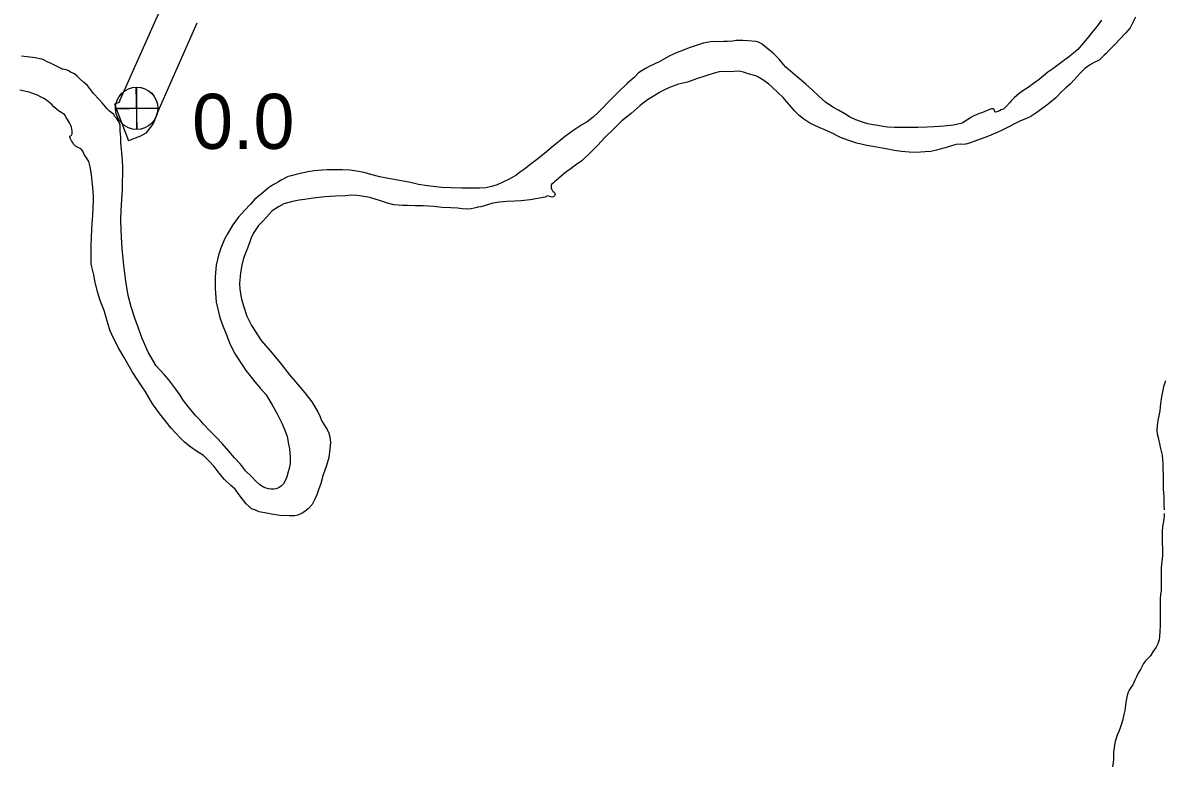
# Model space of a CAD drawing. Extents: x -939622 to -934222, y 1383701 to 1385301.
# Drawn here: x -935712.73 to -935686.47, y 1384159.44 to 1384176.56 of the extents above; entities that cross this region are included whole.
import ezdxf

# ---------------------------------------------------------------- set-up
doc = ezdxf.new("R2010")
doc.units = 0
for name, color, linetype in [('Level 10', 7, 'Continuous'), ('Level 25', 7, 'Continuous'), ('Level 26', 7, 'Continuous'), ('Level 9', 7, 'Continuous')]:
    doc.layers.add(name, color=color, linetype=linetype)

msp = doc.modelspace()

# ---------------------------------------------------------------- linework, layer by layer
at = {"layer": 'Level 10'}
for points in [[(-935709.55, 1384176.91), (-935710.495, 1384174.776), (-935710.512, 1384174.722), (-935710.62, 1384174.681)], [(-935708.727, 1384176.546), (-935709.651, 1384174.459), (-935709.679, 1384174.37), (-935709.719, 1384174.267), (-935709.77, 1384174.182), (-935709.82, 1384174.114), (-935709.902, 1384174.018), (-935710.02, 1384173.946), (-935710.149, 1384173.898), (-935710.297, 1384173.841)], [(-935710.62, 1384174.681), (-935710.297, 1384173.841)]]:
    msp.add_lwpolyline(points, dxfattribs=at)
at = {"layer": 'Level 25'}
for p, q in [((-935710.099, 1384174.1), (-935710.122, 1384175.077)), ((-935710.599, 1384174.577), (-935709.622, 1384174.6))]:
    msp.add_line(p, q, dxfattribs=at)
msp.add_circle((-935710.11, 1384174.589), 0.488, dxfattribs=at)
at = {"layer": 'Level 26'}
for p, q in [((-935710.11, 1384174.101), (-935710.11, 1384175.076)), ((-935710.598, 1384174.589), (-935709.623, 1384174.589))]:
    msp.add_line(p, q, dxfattribs=at)
msp.add_circle((-935710.11, 1384174.589), 0.487, dxfattribs=at)
at = {"layer": 'Level 9'}
for points in [[(-935687.124, 1384176.684), (-935687.202, 1384176.535), (-935687.251, 1384176.441), (-935687.354, 1384176.316), (-935687.492, 1384176.171), (-935687.583, 1384176.07), (-935687.653, 1384176.003), (-935687.741, 1384175.92), (-935687.803, 1384175.852), (-935687.847, 1384175.809), (-935687.959, 1384175.699), (-935688.074, 1384175.642), (-935688.181, 1384175.583), (-935688.29, 1384175.506), (-935688.399, 1384175.395), (-935688.54, 1384175.248), (-935688.631, 1384175.144), (-935688.731, 1384175.058), (-935688.831, 1384174.971), (-935688.96, 1384174.833), (-935689.087, 1384174.722), (-935689.169, 1384174.664), (-935689.281, 1384174.574), (-935689.42, 1384174.478), (-935689.533, 1384174.401), (-935689.637, 1384174.357), (-935689.77, 1384174.3), (-935689.898, 1384174.237), (-935690.028, 1384174.171), (-935690.117, 1384174.127), (-935690.192, 1384174.087), (-935690.295, 1384174.037), (-935690.51, 1384173.951), (-935690.822, 1384173.834), (-935690.905, 1384173.805), (-935691, 1384173.773), (-935691.009, 1384173.767), (-935691.069, 1384173.757), (-935691.147, 1384173.761), (-935691.258, 1384173.753), (-935691.407, 1384173.708), (-935691.505, 1384173.679), (-935691.6, 1384173.653), (-935691.705, 1384173.627), (-935691.833, 1384173.597), (-935691.965, 1384173.585), (-935692.075, 1384173.577), (-935692.192, 1384173.572), (-935692.336, 1384173.581), (-935692.507, 1384173.593), (-935692.682, 1384173.62), (-935692.826, 1384173.647), (-935692.955, 1384173.668), (-935693.127, 1384173.698), (-935693.31, 1384173.731), (-935693.542, 1384173.783), (-935693.726, 1384173.846), (-935693.917, 1384173.92), (-935694.138, 1384174.03), (-935694.262, 1384174.082), (-935694.404, 1384174.146), (-935694.618, 1384174.244), (-935694.755, 1384174.337), (-935694.868, 1384174.425), (-935694.972, 1384174.532), (-935695.046, 1384174.624), (-935695.159, 1384174.748), (-935695.236, 1384174.84), (-935695.352, 1384174.946), (-935695.484, 1384175.079), (-935695.56, 1384175.146), (-935695.676, 1384175.228), (-935695.815, 1384175.313), (-935695.866, 1384175.333), (-935696.038, 1384175.381), (-935696.15, 1384175.421), (-935696.237, 1384175.443), (-935696.486, 1384175.432), (-935696.573, 1384175.433), (-935696.705, 1384175.425), (-935696.824, 1384175.401), (-935697.011, 1384175.337), (-935697.229, 1384175.264), (-935697.437, 1384175.194), (-935697.64, 1384175.142), (-935697.851, 1384175.065), (-935697.994, 1384174.996), (-935698.077, 1384174.952), (-935698.204, 1384174.878), (-935698.352, 1384174.781), (-935698.526, 1384174.652), (-935698.729, 1384174.47), (-935698.944, 1384174.3), (-935699.132, 1384174.113)], [(-935687.905, 1384176.621), (-935688.004, 1384176.48), (-935688.121, 1384176.34), (-935688.241, 1384176.196), (-935688.455, 1384175.945), (-935688.552, 1384175.856), (-935688.667, 1384175.769), (-935688.782, 1384175.68), (-935689.03, 1384175.497), (-935689.143, 1384175.417), (-935689.34, 1384175.25), (-935689.476, 1384175.16), (-935689.597, 1384175.071), (-935689.698, 1384175.005), (-935689.804, 1384174.928), (-935689.916, 1384174.833), (-935689.981, 1384174.768), (-935690.025, 1384174.716), (-935690.086, 1384174.643), (-935690.121, 1384174.609), (-935690.165, 1384174.572), (-935690.213, 1384174.553), (-935690.252, 1384174.534), (-935690.296, 1384174.518), (-935690.32, 1384174.509), (-935690.35, 1384174.502), (-935690.362, 1384174.505), (-935690.365, 1384174.514), (-935690.368, 1384174.532), (-935690.372, 1384174.547), (-935690.378, 1384174.562), (-935690.393, 1384174.576), (-935690.402, 1384174.579), (-935690.441, 1384174.576), (-935690.459, 1384174.569), (-935690.593, 1384174.515), (-935690.649, 1384174.493), (-935690.715, 1384174.468), (-935690.795, 1384174.439), (-935690.849, 1384174.414), (-935690.896, 1384174.383), (-935691.118, 1384174.249), (-935691.312, 1384174.2), (-935691.53, 1384174.178), (-935691.755, 1384174.164), (-935691.919, 1384174.152), (-935692.138, 1384174.148), (-935692.33, 1384174.147), (-935692.515, 1384174.144), (-935692.671, 1384174.146), (-935692.836, 1384174.158), (-935692.933, 1384174.171), (-935693.053, 1384174.193), (-935693.161, 1384174.212), (-935693.287, 1384174.228), (-935693.405, 1384174.268), (-935693.565, 1384174.322), (-935693.704, 1384174.391), (-935693.814, 1384174.461), (-935693.962, 1384174.543), (-935694.09, 1384174.612), (-935694.26, 1384174.732), (-935694.409, 1384174.871), (-935694.562, 1384175.009), (-935694.712, 1384175.142), (-935694.864, 1384175.274), (-935695.008, 1384175.395), (-935695.172, 1384175.536), (-935695.225, 1384175.601), (-935695.326, 1384175.72), (-935695.439, 1384175.835), (-935695.546, 1384175.929), (-935695.653, 1384176.014), (-935695.714, 1384176.067), (-935695.801, 1384176.111), (-935695.862, 1384176.125), (-935696.042, 1384176.139), (-935696.162, 1384176.149), (-935696.315, 1384176.149), (-935696.392, 1384176.138), (-935696.518, 1384176.127), (-935696.608, 1384176.125), (-935696.746, 1384176.119), (-935696.842, 1384176.123), (-935696.904, 1384176.119), (-935697.078, 1384176.092), (-935697.372, 1384175.99), (-935697.714, 1384175.862), (-935697.869, 1384175.784), (-935698.07, 1384175.669), (-935698.302, 1384175.562), (-935698.405, 1384175.506), (-935698.559, 1384175.403), (-935698.656, 1384175.305), (-935698.824, 1384175.157)], [(-935712.758, 1384175.796), (-935712.632, 1384175.778), (-935712.448, 1384175.759), (-935712.298, 1384175.73), (-935712.231, 1384175.698), (-935712.182, 1384175.669), (-935712.1, 1384175.635), (-935712.055, 1384175.615), (-935711.982, 1384175.572), (-935711.811, 1384175.489)], [(-935707.077, 1384165.827), (-935707.131, 1384165.844), (-935707.192, 1384165.87), (-935707.277, 1384165.923), (-935707.371, 1384166.005), (-935707.472, 1384166.109), (-935707.604, 1384166.241), (-935707.721, 1384166.399), (-935707.859, 1384166.54), (-935707.991, 1384166.697), (-935708.141, 1384166.869), (-935708.264, 1384167.002), (-935708.426, 1384167.164), (-935708.573, 1384167.318), (-935708.653, 1384167.407), (-935708.748, 1384167.507), (-935708.895, 1384167.682), (-935709.04, 1384167.872), (-935709.111, 1384167.985), (-935709.231, 1384168.151), (-935709.373, 1384168.335), (-935709.474, 1384168.456), (-935709.661, 1384168.66), (-935709.85, 1384168.972), (-935709.986, 1384169.289), (-935710.062, 1384169.501), (-935710.145, 1384169.734), (-935710.237, 1384170.015), (-935710.305, 1384170.276), (-935710.363, 1384170.612), (-935710.407, 1384170.981), (-935710.434, 1384171.273), (-935710.453, 1384171.483), (-935710.468, 1384171.784), (-935710.473, 1384172.021), (-935710.468, 1384172.247), (-935710.455, 1384172.479), (-935710.439, 1384172.708), (-935710.434, 1384172.901), (-935710.431, 1384173.076), (-935710.431, 1384173.226), (-935710.441, 1384173.394), (-935710.45, 1384173.557), (-935710.461, 1384173.647), (-935710.473, 1384173.791), (-935710.475, 1384173.917), (-935710.483, 1384174.002), (-935710.488, 1384174.071), (-935710.49, 1384174.203), (-935710.5, 1384174.224), (-935710.516, 1384174.269), (-935710.534, 1384174.299), (-935710.577, 1384174.358), (-935710.617, 1384174.402), (-935710.645, 1384174.45), (-935710.733, 1384174.52), (-935710.792, 1384174.576), (-935710.905, 1384174.716), (-935710.973, 1384174.793), (-935711.104, 1384174.931), (-935711.24, 1384175.112), (-935711.332, 1384175.192), (-935711.408, 1384175.26), (-935711.484, 1384175.33), (-935711.539, 1384175.38), (-935711.633, 1384175.421), (-935711.672, 1384175.45), (-935711.73, 1384175.473), (-935711.811, 1384175.489)], [(-935711.775, 1384174.443), (-935711.908, 1384174.53), (-935712.015, 1384174.626), (-935712.068, 1384174.682), (-935712.147, 1384174.747), (-935712.233, 1384174.805), (-935712.324, 1384174.85), (-935712.397, 1384174.888), (-935712.503, 1384174.933), (-935712.582, 1384174.961), (-935712.663, 1384174.977), (-935712.799, 1384175.004)], [(-935698.824, 1384175.157), (-935699.033, 1384174.961), (-935699.139, 1384174.856), (-935699.268, 1384174.724), (-935699.373, 1384174.611), (-935699.485, 1384174.5), (-935699.603, 1384174.387), (-935699.747, 1384174.281), (-935699.869, 1384174.207), (-935700.076, 1384174.073), (-935700.244, 1384173.944), (-935700.53, 1384173.715), (-935700.727, 1384173.549), (-935700.91, 1384173.404), (-935701.067, 1384173.289), (-935701.188, 1384173.185), (-935701.279, 1384173.123), (-935701.388, 1384173.039), (-935701.551, 1384172.949), (-935701.688, 1384172.886), (-935701.819, 1384172.826), (-935701.947, 1384172.785), (-935702.075, 1384172.758), (-935702.225, 1384172.752), (-935702.473, 1384172.747), (-935702.632, 1384172.75), (-935702.881, 1384172.757), (-935703.094, 1384172.768), (-935703.419, 1384172.801), (-935703.629, 1384172.836), (-935703.81, 1384172.88), (-935704.105, 1384172.935), (-935704.363, 1384172.984), (-935704.514, 1384173.011), (-935704.719, 1384173.064), (-935704.878, 1384173.109), (-935705.056, 1384173.142), (-935705.2, 1384173.163), (-935705.377, 1384173.172), (-935705.566, 1384173.174), (-935705.725, 1384173.174), (-935705.854, 1384173.168), (-935706.03, 1384173.147), (-935706.173, 1384173.123), (-935706.343, 1384173.084), (-935706.439, 1384173.064), (-935706.555, 1384173.031), (-935706.627, 1384173.018), (-935706.671, 1384172.999), (-935706.787, 1384172.933), (-935706.849, 1384172.893), (-935706.988, 1384172.818), (-935707.077, 1384172.756), (-935707.248, 1384172.611), (-935707.39, 1384172.497), (-935707.495, 1384172.381), (-935707.627, 1384172.237), (-935707.697, 1384172.157), (-935707.776, 1384172.071), (-935707.902, 1384171.903), (-935708.021, 1384171.702), (-935708.087, 1384171.574), (-935708.176, 1384171.365), (-935708.229, 1384171.21), (-935708.285, 1384170.981), (-935708.306, 1384170.709), (-935708.307, 1384170.444), (-935708.282, 1384170.129), (-935708.197, 1384169.775), (-935708.13, 1384169.584), (-935708.061, 1384169.411), (-935707.976, 1384169.19), (-935707.86, 1384168.951), (-935707.742, 1384168.776), (-935707.671, 1384168.663), (-935707.597, 1384168.55), (-935707.501, 1384168.426), (-935707.391, 1384168.292), (-935707.259, 1384168.141), (-935707.139, 1384167.996), (-935707.059, 1384167.874), (-935706.981, 1384167.735), (-935706.881, 1384167.556), (-935706.772, 1384167.341), (-935706.7, 1384167.18), (-935706.649, 1384167.034), (-935706.615, 1384166.86), (-935706.598, 1384166.749), (-935706.582, 1384166.556), (-935706.579, 1384166.415), (-935706.601, 1384166.294), (-935706.623, 1384166.222), (-935706.654, 1384166.107), (-935706.7, 1384165.994), (-935706.732, 1384165.946), (-935706.776, 1384165.897), (-935706.832, 1384165.856), (-935706.903, 1384165.825), (-935706.954, 1384165.821), (-935707.02, 1384165.819), (-935707.077, 1384165.827)], [(-935711.629, 1384174.196), (-935711.66, 1384174.255), (-935711.701, 1384174.333), (-935711.741, 1384174.392), (-935711.756, 1384174.422), (-935711.775, 1384174.443)], [(-935705.816, 1384167.339), (-935705.757, 1384167.238), (-935705.729, 1384167.193), (-935705.691, 1384167.107), (-935705.666, 1384167.023), (-935705.654, 1384166.891), (-935705.666, 1384166.746), (-935705.692, 1384166.55), (-935705.742, 1384166.368), (-935705.827, 1384166.126), (-935705.875, 1384165.953), (-935705.929, 1384165.802), (-935705.962, 1384165.69), (-935706.008, 1384165.593), (-935706.072, 1384165.465), (-935706.163, 1384165.37), (-935706.242, 1384165.305), (-935706.304, 1384165.268), (-935706.399, 1384165.224), (-935706.48, 1384165.21), (-935706.603, 1384165.205), (-935706.816, 1384165.212), (-935707.011, 1384165.245), (-935707.162, 1384165.275), (-935707.255, 1384165.291), (-935707.291, 1384165.299), (-935707.376, 1384165.334), (-935707.379, 1384165.334), (-935707.466, 1384165.368), (-935707.478, 1384165.374), (-935707.512, 1384165.41), (-935707.591, 1384165.48), (-935707.755, 1384165.691), (-935707.847, 1384165.818), (-935707.948, 1384165.907), (-935708.088, 1384166.045), (-935708.214, 1384166.19), (-935708.331, 1384166.339), (-935708.451, 1384166.475), (-935708.57, 1384166.596), (-935708.731, 1384166.695), (-935708.865, 1384166.789), (-935709.011, 1384166.906), (-935709.118, 1384167.012), (-935709.317, 1384167.222), (-935709.579, 1384167.551), (-935709.745, 1384167.786), (-935709.916, 1384168.074), (-935709.972, 1384168.154), (-935710.089, 1384168.336), (-935710.21, 1384168.514), (-935710.328, 1384168.725), (-935710.396, 1384168.85), (-935710.523, 1384169.056), (-935710.648, 1384169.3), (-935710.724, 1384169.464), (-935710.765, 1384169.611), (-935710.817, 1384169.772), (-935710.862, 1384169.931), (-935710.951, 1384170.164), (-935711.005, 1384170.337), (-935711.064, 1384170.577), (-935711.1, 1384170.751), (-935711.156, 1384170.997), (-935711.159, 1384171.147), (-935711.159, 1384171.261), (-935711.159, 1384171.427), (-935711.148, 1384171.614), (-935711.146, 1384171.797), (-935711.133, 1384171.936), (-935711.122, 1384172.126), (-935711.111, 1384172.301), (-935711.105, 1384172.445), (-935711.104, 1384172.566), (-935711.109, 1384172.668), (-935711.117, 1384172.764), (-935711.146, 1384172.977), (-935711.153, 1384173.067), (-935711.184, 1384173.241), (-935711.197, 1384173.301), (-935711.211, 1384173.367), (-935711.251, 1384173.424), (-935711.316, 1384173.528), (-935711.334, 1384173.566), (-935711.35, 1384173.599), (-935711.378, 1384173.641), (-935711.405, 1384173.661), (-935711.466, 1384173.69), (-935711.517, 1384173.719), (-935711.557, 1384173.755), (-935711.588, 1384173.808), (-935711.61, 1384173.838), (-935711.635, 1384173.886), (-935711.653, 1384173.924), (-935711.648, 1384173.946), (-935711.63, 1384173.958), (-935711.609, 1384173.973), (-935711.595, 1384174.001), (-935711.599, 1384174.067), (-935711.613, 1384174.145), (-935711.629, 1384174.196)], [(-935699.132, 1384174.113), (-935699.332, 1384173.928), (-935699.505, 1384173.732), (-935699.661, 1384173.576), (-935699.864, 1384173.382), (-935700.015, 1384173.28), (-935700.144, 1384173.178), (-935700.201, 1384173.141), (-935700.286, 1384173.07), (-935700.404, 1384172.974), (-935700.457, 1384172.928), (-935700.492, 1384172.897), (-935700.519, 1384172.876), (-935700.563, 1384172.833), (-935700.569, 1384172.815), (-935700.574, 1384172.793), (-935700.574, 1384172.781), (-935700.573, 1384172.754), (-935700.57, 1384172.742), (-935700.558, 1384172.719), (-935700.542, 1384172.692), (-935700.53, 1384172.677), (-935700.505, 1384172.656), (-935700.487, 1384172.63), (-935700.487, 1384172.627), (-935700.483, 1384172.609), (-935700.495, 1384172.575), (-935700.515, 1384172.554), (-935700.551, 1384172.541), (-935700.602, 1384172.561), (-935700.654, 1384172.572), (-935700.71, 1384172.544), (-935701.053, 1384172.48), (-935701.122, 1384172.476), (-935701.26, 1384172.461), (-935701.412, 1384172.452), (-935701.592, 1384172.442), (-935701.763, 1384172.43), (-935701.918, 1384172.403), (-935702.061, 1384172.361), (-935702.192, 1384172.319), (-935702.264, 1384172.309), (-935702.273, 1384172.306), (-935702.413, 1384172.276), (-935702.5, 1384172.268), (-935702.617, 1384172.278), (-935702.731, 1384172.288), (-935702.878, 1384172.294), (-935703.082, 1384172.305), (-935703.271, 1384172.325), (-935703.52, 1384172.341), (-935703.7, 1384172.341), (-935703.88, 1384172.349), (-935703.997, 1384172.353), (-935704.192, 1384172.364), (-935704.337, 1384172.401), (-935704.524, 1384172.463), (-935704.62, 1384172.494), (-935704.747, 1384172.534), (-935704.93, 1384172.566), (-935705.041, 1384172.579), (-935705.165, 1384172.592), (-935705.311, 1384172.577), (-935705.536, 1384172.564), (-935705.784, 1384172.553), (-935706.05, 1384172.52), (-935706.251, 1384172.492), (-935706.37, 1384172.475), (-935706.528, 1384172.445), (-935706.722, 1384172.387), (-935706.846, 1384172.318), (-935706.994, 1384172.225), (-935707.199, 1384171.995), (-935707.241, 1384171.961), (-935707.305, 1384171.894), (-935707.433, 1384171.708), (-935707.473, 1384171.608), (-935707.516, 1384171.489), (-935707.579, 1384171.329), (-935707.65, 1384171.138), (-935707.688, 1384170.974), (-935707.721, 1384170.799), (-935707.743, 1384170.552), (-935707.737, 1384170.42), (-935707.699, 1384170.195), (-935707.645, 1384170.015), (-935707.575, 1384169.806), (-935707.471, 1384169.591), (-935707.248, 1384169.24), (-935706.991, 1384168.95), (-935706.806, 1384168.725), (-935706.594, 1384168.449), (-935706.367, 1384168.183), (-935706.241, 1384168.038), (-935706.081, 1384167.833), (-935705.988, 1384167.679), (-935705.944, 1384167.601), (-935705.891, 1384167.485), (-935705.882, 1384167.464), (-935705.859, 1384167.404), (-935705.816, 1384167.339)], [(-935686.433, 1384168.312), (-935686.481, 1384168.173), (-935686.53, 1384167.946), (-935686.548, 1384167.792), (-935686.563, 1384167.627), (-935686.582, 1384167.545), (-935686.615, 1384167.403), (-935686.628, 1384167.288), (-935686.631, 1384167.174), (-935686.627, 1384167.096), (-935686.607, 1384167.009), (-935686.587, 1384166.931), (-935686.571, 1384166.871), (-935686.555, 1384166.79), (-935686.509, 1384166.604), (-935686.496, 1384166.415), (-935686.496, 1384166.292), (-935686.487, 1384166.132), (-935686.487, 1384165.991), (-935686.487, 1384165.825), (-935686.477, 1384165.645), (-935686.471, 1384165.461), (-935686.465, 1384165.344)], [(-935686.463, 1384165.257), (-935686.468, 1384165.202), (-935686.481, 1384165.079), (-935686.502, 1384164.958), (-935686.512, 1384164.849), (-935686.51, 1384164.759), (-935686.508, 1384164.636), (-935686.506, 1384164.392), (-935686.507, 1384164.29), (-935686.519, 1384164.154), (-935686.534, 1384164.015), (-935686.538, 1384163.916), (-935686.533, 1384163.835), (-935686.534, 1384163.708), (-935686.535, 1384163.621), (-935686.533, 1384163.534), (-935686.538, 1384163.47), (-935686.549, 1384163.401), (-935686.561, 1384163.295), (-935686.557, 1384163.235), (-935686.556, 1384163.157), (-935686.554, 1384163.064), (-935686.557, 1384162.919), (-935686.56, 1384162.781), (-935686.561, 1384162.681), (-935686.564, 1384162.546), (-935686.571, 1384162.425), (-935686.584, 1384162.35), (-935686.612, 1384162.262), (-935686.653, 1384162.186), (-935686.725, 1384162.076), (-935686.781, 1384161.985), (-935686.898, 1384161.868), (-935686.939, 1384161.81), (-935686.982, 1384161.728), (-935687.014, 1384161.667), (-935687.057, 1384161.6), (-935687.106, 1384161.503), (-935687.138, 1384161.421), (-935687.164, 1384161.372), (-935687.19, 1384161.318), (-935687.21, 1384161.284), (-935687.23, 1384161.254), (-935687.268, 1384161.196), (-935687.291, 1384161.147), (-935687.316, 1384161.071), (-935687.328, 1384161.029), (-935687.346, 1384160.914), (-935687.362, 1384160.785), (-935687.372, 1384160.721), (-935687.391, 1384160.636), (-935687.408, 1384160.567), (-935687.419, 1384160.519), (-935687.447, 1384160.416), (-935687.475, 1384160.325), (-935687.512, 1384160.24), (-935687.547, 1384160.158), (-935687.592, 1384160.013), (-935687.605, 1384159.937), (-935687.619, 1384159.867), (-935687.629, 1384159.765), (-935687.632, 1384159.657), (-935687.631, 1384159.596), (-935687.636, 1384159.53), (-935687.655, 1384159.43)]]:
    msp.add_lwpolyline(points, dxfattribs=at)

# ---------------------------------------------------------------- texts
at = {"layer": 'Level 25'}
msp.add_text('0.0', height=1.2672, dxfattribs=at).set_placement((-935708.836, 1384173.655))

doc.saveas('drawing.dxf')
